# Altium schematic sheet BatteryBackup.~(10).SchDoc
size 431 x 279 mm; Date: Not shown in title block; ApprovedBy: Not shown in title block; CheckedBy: Not shown in title block; Author: Not shown in title block; CompanyName: Not shown in title block; Engineer: Not shown in title block; Organization: Not shown in title block; Address1: Not shown in title block; Address2: Not shown in title block; Address3: Not shown in title block; Address4: Not shown in title block; DocumentNumber: 1; Revision: Use project parameter SCH_Rev; SheetNumber: 1; SheetTotal: 2; PageSetup: Record=PageOptions¦CenterHorizontal=True¦CenterVertical=True¦PrintScale=1.00¦XCorrection=1.00¦YCorrection=1.00¦PrintKind=0¦BorderSize=5000000¦LeftOffset=0¦BottomOffset=0¦Orientation=2¦PaperLength=1000¦PaperWidth=1000¦Scale=100¦PaperSource=15¦PrintQuality=600¦MediaType=1¦DitherType=10¦PaperKind=Letter¦PrintScaleMode=1
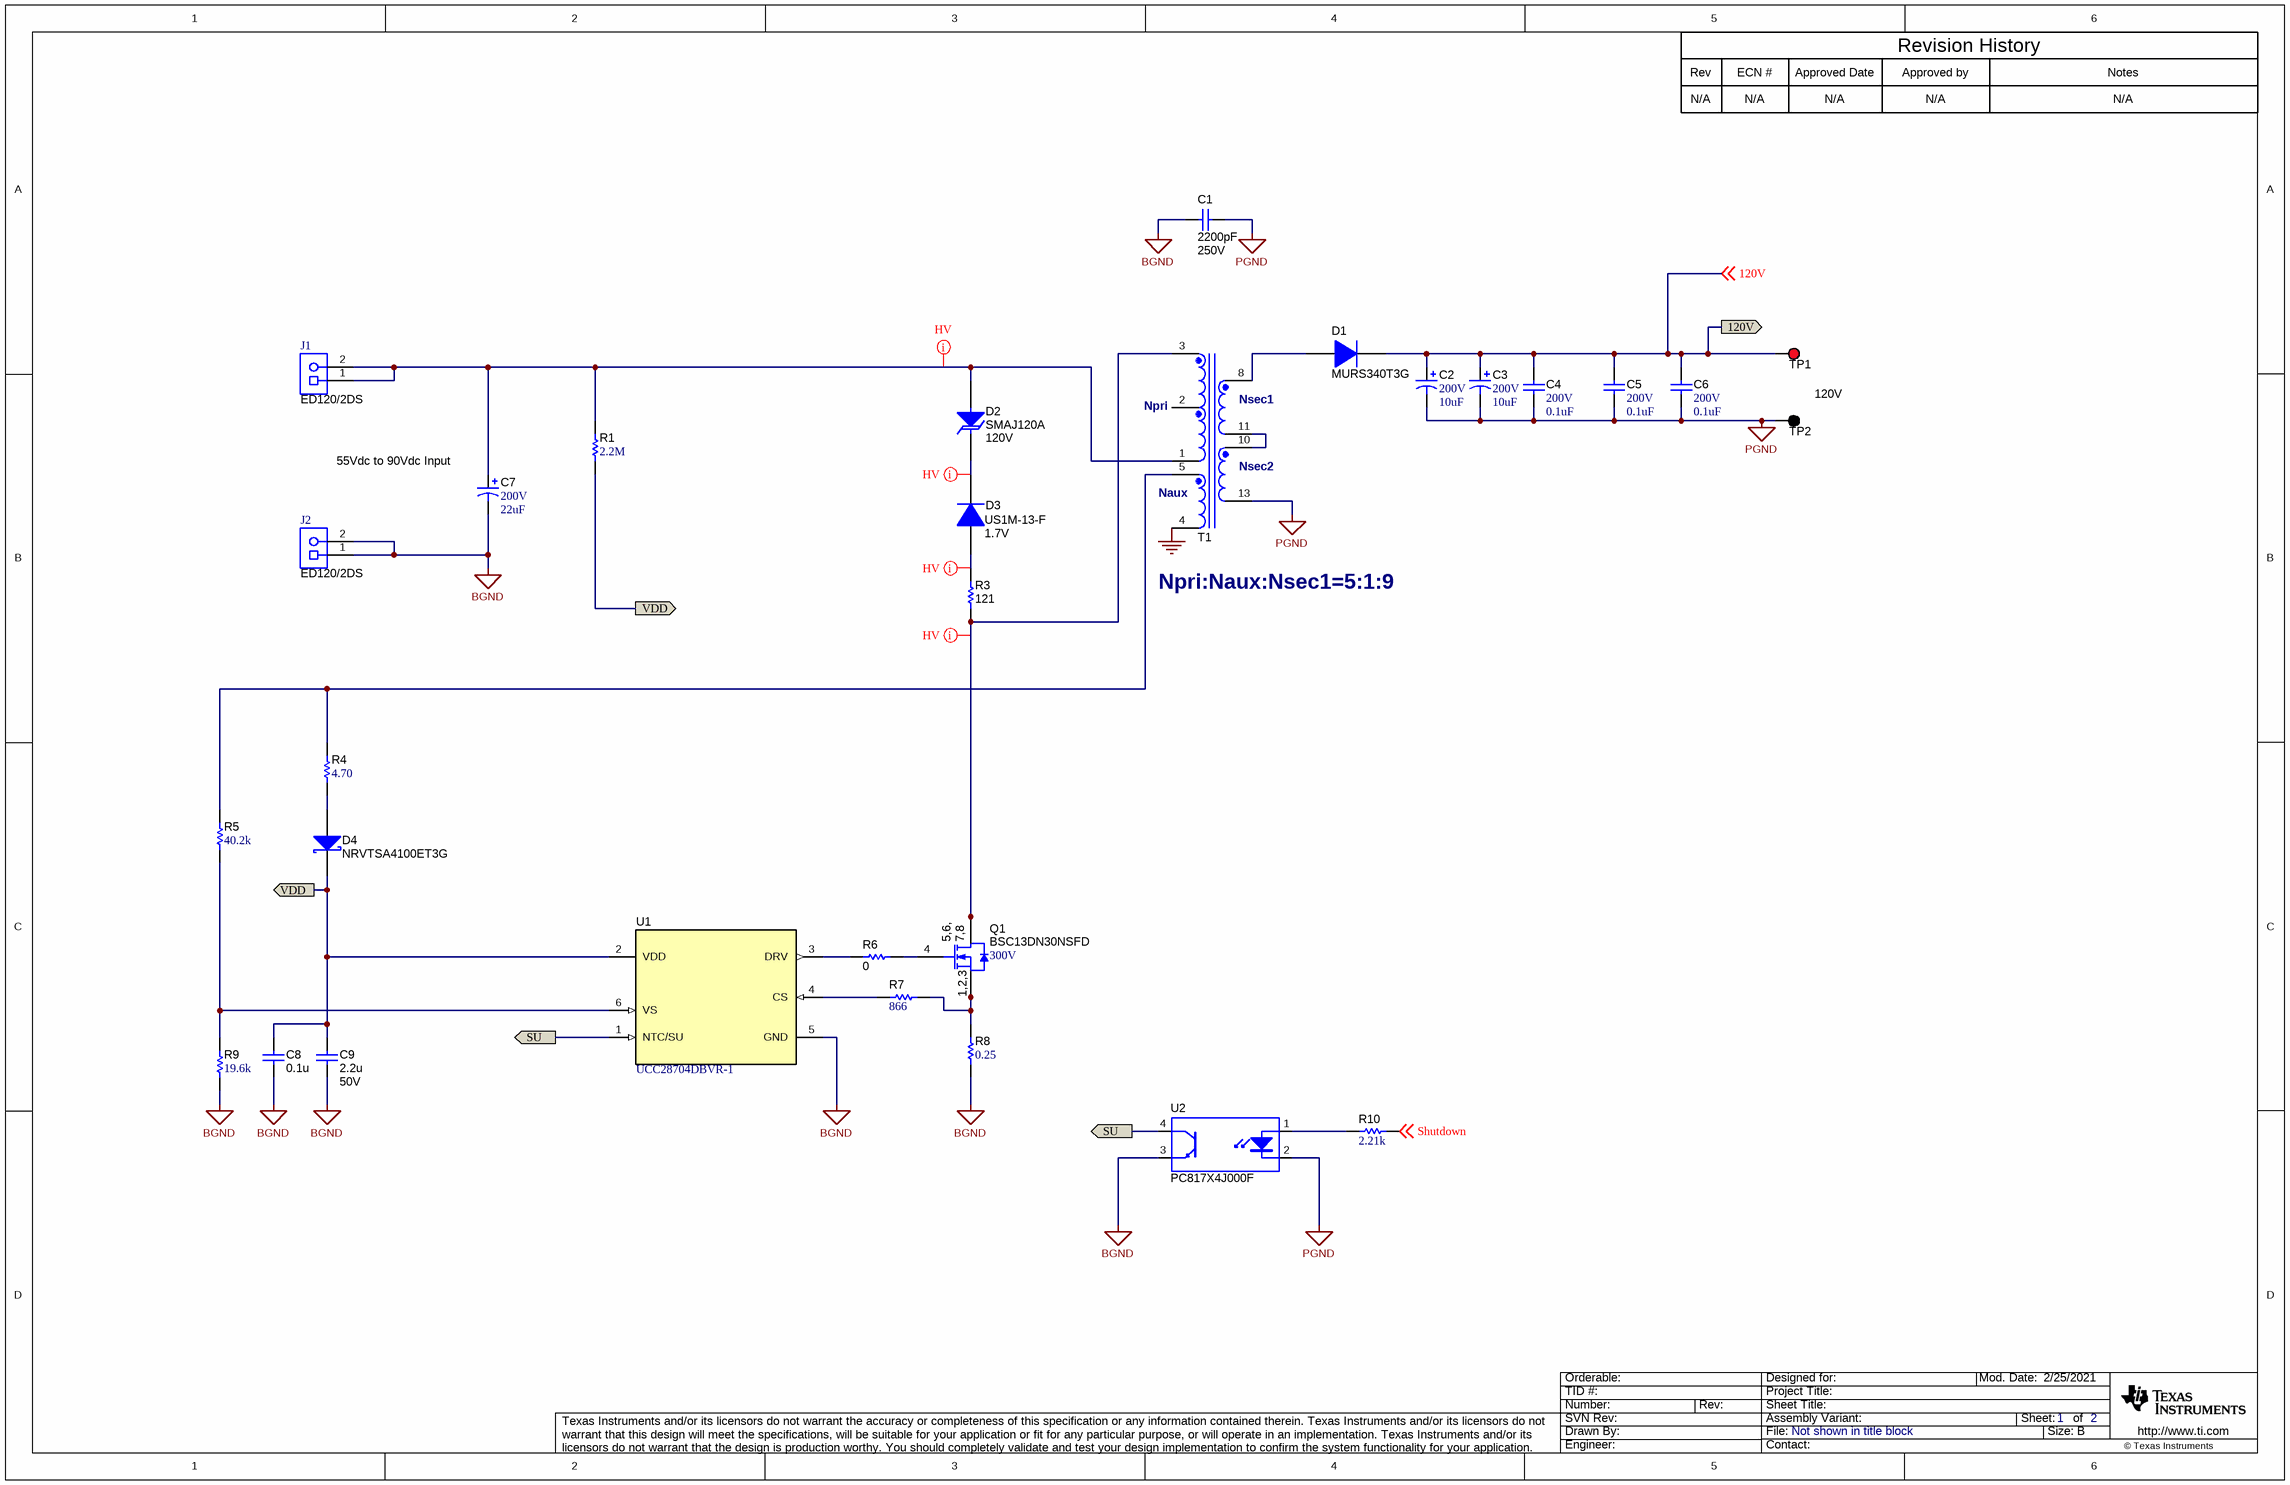
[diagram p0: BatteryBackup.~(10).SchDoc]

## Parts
C1  ValueDisplayed: 2200pF  Value2: 250V  [CAPRD750W60D1050H1450]  (hidden comment: CS11-E2GA222MYNS)
C2  VDC_V: 200V  ValueDisplayed: 10uF  [VK_800X1150]  (hidden comment: UVK2D100MPD)
C3  VDC_V: 200V  ValueDisplayed: 10uF  [VK_800X1150]  (hidden comment: UVK2D100MPD)
C4  VDC_V: 200V  ValueDisplayed: 0.1uF  [1206]  (hidden comment: C1206C104K2RACTU)
C5  VDC_V: 200V  ValueDisplayed: 0.1uF  [1206]  (hidden comment: C1206C104K2RACTU)
C6  VDC_V: 200V  ValueDisplayed: 0.1uF  [1206]  (hidden comment: C1206C104K2RACTU)
C7  VDC_V: 200V  ValueDisplayed: 22uF  [UPW_1000x2000]  (hidden comment: UPW2D220MPD1TD)
C8  ValueDisplayed: 0.1u  [0603]  (hidden comment: 06035C104KAT2A)
C9  ValueDisplayed: 2.2u  Value2: 50V  [1206]  (hidden comment: GRM31CR61H225KA88L)
D1  MURS340T3G  [SMC]
D2  SMAJ120A  value 120V  [SMA]
D3  US1M-13-F  value 1.7V  [SMA]
D4  NRVTSA4100ET3G  [SMA]
J1  ED120/2DS  [On-Shore_ED120_2DS]
J2  ED120/2DS  [On-Shore_ED120_2DS]
Q1  BSC13DN30NSFD  value 300V  [PG-TDSON-8]
R1  ValueDisplayed: 2.2M  [1206]  (hidden comment: CRCW12062M20JNEA)
R3  value 121  [1206]  (hidden comment: CRCW1206121RFKEA)
R4  ValueDisplayed: 4.70  [1206]  (hidden comment: RC1206FR-074R7L)
R5  ValueDisplayed: 40.2k  [0603]  (hidden comment: RC0603FR-0740K2L)
R6  value 0  [0603]  (hidden comment: CRCW06030000Z0EA)
R7  ValueDisplayed: 866  [0603]  (hidden comment: RC0603FR-07866RL)
R8  ValueDisplayed: 0.25  [1206]  (hidden comment: CSR1206FKR250)
R9  ValueDisplayed: 19.6k  [0603]  (hidden comment: RC0603FR-0719K6L)
R10  ValueDisplayed: 2.21k  [0603]  (hidden comment: RC0603FR-072K21L)
T1  750314727  [WURTH_750314727]  (value not drawn)
TP1  5000  [Keystone5000]  (value not drawn)
TP2  5001  [Keystone5001]  (value not drawn)
U1  UCC28704DBVR-1  [DBV0006A_N]
U2  PC817X4J000F  [DIP762W60P254L460H350Q4B]

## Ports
120V (out), SU (out), VDD (out)

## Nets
BGND: C1.2 C7.2(-) C8.2 C9.2 J2.1 J2.2 R8.1 R9.1 U1.5(GND) U2.3(E)
GND: T1.4
PGND: C1.1 C2.2(-) C3.2(-) C4.2 C5.2 C6.2 T1.13 TP2.1 U2.2(K)
120V: C2.1(+) C3.1(+) C4.1 C5.1 C6.1 D1.1(K) TP1.1 ; off-sheet 120V, port 120V
Shutdown: R10.2 ; off-sheet Shutdown
SU: U1.1(NTC/SU) U2.4(C) ; port SU
VDD: C8.1 C9.1 D4.1(K) R1.1 U1.2(VDD) ; port VDD
NetC7_1: C7.1(+) D2.2(A) J1.1 J1.2 R1.2 T1.1
NetD1_2: D1.2(A) T1.8
NetD2_1: D2.1(K) D3.1(K)
NetD3_2: D3.2(A) R3.2
NetD4_2: D4.2(A) R4.1
NetQ1_1: Q1.1(S) Q1.2(S) Q1.3(S) R7.2 R8.2
NetQ1_4: Q1.4(G) R6.2
NetQ1_5: Q1.5(D) Q1.6(D) Q1.7(D) Q1.8(D) Q1.9(D) R3.1 T1.3
NetR4_2: R4.2 R5.2 T1.5
NetR5_1: R5.1 R9.2 U1.6(VS)
NetR6_1: R6.1 U1.3(DRV)
NetR7_1: R7.1 U1.4(CS)
NetR10_1: R10.1 U2.1(A)
NetT1_10: T1.10 T1.11

Not connected (* = marked no-connect by the designer): T1 2

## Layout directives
net class HV: NetC7_1, NetD2_1, NetD3_2, NetQ1_5

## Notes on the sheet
- Rev
- N/A
- ECN #
- Approved Date
- Approved by
- Revision History
- Notes
- (near T1) Npri
- (near T1) Nsec1
- 120V
- (near C7) 55Vdc to 90Vdc Input
- (near T1) Naux
- (near T1) Nsec2
- (near T1) Npri:Naux:Nsec1=5:1:9

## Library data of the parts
C1 = CS11-E2GA222MYNS: CAP, CERM, 2200pF, 250V, +/-20%, E, Radial Disc D10.5x7mm; Manufacturer: TDK; Polarized: N; CompType: Capacitor; U/M: EA; Cap_F: 0.0000000022; Tolerance_%: 20; Value1: Unknown; VDC_V: 250; TaMin_C: -25; TaMax_C: 105; Cap_Case: Disc, 10.5x7mm
C2 C3 = CMP-0064891-1: CAP, AL, 10 uF, 200 V, +/- 20%, TH; Manufacturer: Nichicon; TaMin_C: -40°C; Polarized: Y; SizeAreaWB_mm2: 100; Value1: Unknown; U/M: EA; Value: 10uF; TaMax_C: 85°C; SizeZ_mm: 13; SizeX_mm: 8; Cap_Case: 8x11.5mm; SizeArea_mm2: 64; CompType: Capacitor; AEC Qualified: N; Cap_F: 10µF; IRMS_A: 80mA; AEC Category: Q200
C4-C6 = CMP-0008585-2: CAP, CERM, 0.1 uF, 200 V, +/- 10%, X7R, 1206; Manufacturer: Kemet; TaMin_C: -55°C; Polarized: N; SizeAreaWB_mm2: 10.92; Value1: Unknown; U/M: EA; Value: 0.1uF; TaMax_C: 125°C; SizeZ_mm: 1.35; SizeX_mm: 3.2; SizeY_mm: 1.6; SizeArea_mm2: 5.12; Cap_F: 100nF; AEC Category: Q200
C7 = CMP-0064890-1: CAP, AL, 22 uF, 200 V, +/- 20%, TH; Manufacturer: Nichicon; TaMin_C: -40°C; Polarized: Y; SizeAreaWB_mm2: 144; Value1: Unknown; U/M: EA; Value: 22uF; TaMax_C: 105°C; SizeZ_mm: 22; SizeX_mm: 10; Cap_Case: 10x20mm; SizeArea_mm2: 100; CompType: Capacitor; AEC Qualified: N; Cap_F: 22µF; IRMS_A: 1.4dA; AEC Category: Q200
C8 = 06035C104KAT2A: CAP, CERM, 0.1uF, 50V, +/-10%, X7R, 0603; Manufacturer: AVX; Polarized: N; CompType: Capacitor; U/M: EA; Cap_F: 0.0000001; Tolerance_%: 10; Value1: Unknown; VDC_V: 50; TaMin_C: -55; TaMax_C: 125
C9 = GRM31CR61H225KA88L: CAP, CERM, 2.2uF, 50V, +/-10%, X5R, 1206; Manufacturer: MuRata; Polarized: N; CompType: Capacitor; U/M: EA; Cap_F: 0.0000022; Tolerance_%: 10; Value1: Unknown; VDC_V: 50; TaMin_C: -55; TaMax_C: 85
D1 = CMP-0076962-2: Diode, Ultrafast, 400 V, 3 A, SMC; Manufacturer: ON Semiconductor; AEC Category: Q101; Io_A: 3A; RJC_CperW: 11.0; SizeArea_mm2: 50.5686; SizeX_mm: 8.13; SizeZ_mm: 2.6; SizeAreaWB_mm2: 83.2686; TJmax_C: 175°C; Green_REACh: Incomplete; Value2: 1.25V; Vr_V: 400V; Green_Lifecycle: Not Set; SizeY_mm: 6.22; Value: 400V
D2 = SMAJ120A: Diode, TVS, Uni, 120V, 400W, SMA; Manufacturer: Littelfuse; U/M: EA; Power_W: 400; Vr_V: 120
D3 = US1M-13-F: Diode, Ultrafast, 1000V, 1A, SMA; Manufacturer: Diodes Inc.; U/M: EA; Vf_V: 1.7; Io_A: 1; Vr_V: 1000; TJmax_C: 150; RJC_CperW: 30
D4 = CMP-0081057-2: Diode, Schottky, 100 V, 4 A, AEC-Q101, SMA; Manufacturer: ON Semiconductor; SizeZ_mm: 2.87; SizeY_mm: 2.92; SizeAreaWB_mm2: 37.3428; Io_A: 4A; AEC Category: Q101; SizeX_mm: 5.59; Value: 100V; SizeArea_mm2: 16.3228; Value2: 0.68V; TJmax_C: 175°C; AEC Qualified: Y; Vf_V: 680mV
J1 J2 = CMP-0074910-1: Terminal Block, 5.08 mm, 2x1, Brass, TH; Manufacturer: On-Shore Technology; Cert_VDE: Y; CNHeader: False; Current_A: 15A; Green_Lifecycle: Not Set; Shrouded: N; Gender: Female; Green_REACh: Incomplete; Voltage_V: 300V; Row_Count: 1; Pitch_mm: 5.08; CT: True
Q1 = CMP-0000907-1: MOSFET, N-CH, 300 V, 16 A, PG-TDSON-8; Alternate Manufacturer: None; Manufacturer: Infineon Technologies; SizeZ_mm: 1.12; ChType: N; SizeX_mm: 5.99; SizeY_mm: 4.9; Vgs_V: 20V; SizeArea_mm2: 29.351; IdsMax_A: 16A; SizeAreaWB_mm2: 55.131; U/M: EA; QgTyp_nC: 23
R1 = CMP-0018645-3: RES, 2.2 M, 5%, 0.25 W, AEC-Q200 Grade 0, 1206; Manufacturer: Vishay-Dale; Power_W: 250mW; TempCo: 200 ppm/C; Value_Code: 2M20; Value: 2.2Meg; EIA_Code: E24; SizeX_mm: 3.2; SizeY_mm: 1.6; SizeZ_mm: 1.35; Value2: 0.25W; SizeArea_mm2: 5.12; AEC Qualified: Y; VDC_V: 200V; AEC Category: Q200; AEC Grade: 0
R3 = CRCW1206121RFKEA: RES, 121 ohm, 1%, 0.25W, 1206; Manufacturer: Vishay-Dale; CompType: Resistor; Value_Code: 121R; Tolerance_%: 1; Power_W: 0.25; VDC_V: 200; TempCo: 100 ppm/C; EIA_Code: E96; U/M: EA
R4 = CMP-0018350-2: RES, 4.70, 1%, 0.25 W, 1206; Manufacturer: Yageo America; Power_W: 250mW; TempCo: 200 ppm/C; Value_Code: 4R70; U/M: EA; Value: 4.70; Res_ohm: 4.7; SizeX_mm: 3.2; SizeY_mm: 1.6; SizeZ_mm: 1.35; Value2: 0.25W; SizeArea_mm2: 5.12; VDC_V: 200V; AEC Category: Q200
R5 = CMP-0023098-5: RES, 40.2 k, 1%, 0.1 W, 0603; Manufacturer: Yageo; Power_W: 100mW; TempCo: 100 ppm/C; Value_Code: 40k2; Value: 40.2k; EIA_Code: E96; SizeX_mm: 1.6; SizeY_mm: 0.8; SizeZ_mm: 1; Value2: 0.1W; SizeArea_mm2: 1.28; AEC Qualified: N; VDC_V: 75V; AEC Category: Q200; SizeAreaWB_mm2: 4.68
R6 = CRCW06030000Z0EA: RES, 0 ohm, 5%, 0.1W, 0603; Manufacturer: Vishay-Dale; CompType: Resistor; Value_Code: 0000; Tolerance_%: 5; Power_W: 0.1; VDC_V: 75; TempCo: 200 ppm/C; EIA_Code: E24; U/M: EA
R7 = CMP-0023300-5: RES, 866, 1%, 0.1 W, 0603; Manufacturer: Yageo; Power_W: 100mW; TempCo: 100 ppm/C; Value_Code: 866R; Value: 866; EIA_Code: E96; SizeX_mm: 1.6; SizeY_mm: 0.8; SizeZ_mm: 1; Value2: 0.1W; SizeArea_mm2: 1.28; AEC Qualified: N; VDC_V: 75V; AEC Category: Q200; SizeAreaWB_mm2: 4.68
R8 = CMP-0017267-2: RES, 0.25, 1%, 0.5 W, 1206; Manufacturer: Stackpole Electronics Inc; Power_W: 500mW; TempCo: 100 ppm/C; Value_Code: R250; U/M: EA; Value: 0.25; Res_ohm: 2.5d; SizeX_mm: 3.2; SizeY_mm: 1.6; SizeZ_mm: 1.35; Value2: 0.5W; SizeArea_mm2: 5.12; AEC Category: Q200
R9 = CMP-0022861-5: RES, 19.6 k, 1%, 0.1 W, 0603; Manufacturer: Yageo; Power_W: 100mW; TempCo: 100 ppm/C; Value_Code: 19k6; Value: 19.6k; EIA_Code: E96; SizeX_mm: 1.6; SizeY_mm: 0.8; SizeZ_mm: 1; Value2: 0.1W; SizeArea_mm2: 1.28; AEC Qualified: N; VDC_V: 75V; AEC Category: Q200; SizeAreaWB_mm2: 4.68
R10 = CMP-0022984-5: RES, 2.21 k, 1%, 0.1 W, 0603; Manufacturer: Yageo; Power_W: 100mW; TempCo: 100 ppm/C; Value_Code: 2k21; Value: 2.21k; EIA_Code: E96; SizeX_mm: 1.6; SizeY_mm: 0.8; SizeZ_mm: 1; Value2: 0.1W; SizeArea_mm2: 1.28; AEC Qualified: N; VDC_V: 75V; AEC Category: Q200; SizeAreaWB_mm2: 4.68
T1 = 750314727: Transformer, 80uH, TH; Manufacturer: Wurth Elektronik eiSos; SymbolCreator: x0208325; DCR_Ohm: 0.221; Value: 250uH; LeakageL: TBD; U/M: EA
TP1 = 5000: Test Point, TH, Miniature, Red; Manufacturer: Keystone; CompType: Test Point Loop; U/M: EA
TP2 = 5001: Test Point, TH, Miniature, Black; Manufacturer: Keystone; CompType: Test Point Loop; U/M: EA
U1 = CMP-0074087-1: Off-Line Constant-Voltage Constant-Current Flyback Controller With Primary-Side Regulation (PSR), DBV0006A (SOT-23-6); Alternate PartNumber: UCC28704DBVT-1; Alternate Manufacturer: Texas Instruments; Green_Lifecycle: Active; SizeAreaWB_mm2: 14.82; Green_REACh: Passed; U/M: EA; SizeZ_mm: 1.45; SizeX_mm: 2.8; SizeY_mm: 2.9; SizeArea_mm2: 8.12; CompType: IC
U2 = LTV-817: Opto-Isolator, 1 Channel, TH; CompType: OPTOCOUPLER; U/M: EA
